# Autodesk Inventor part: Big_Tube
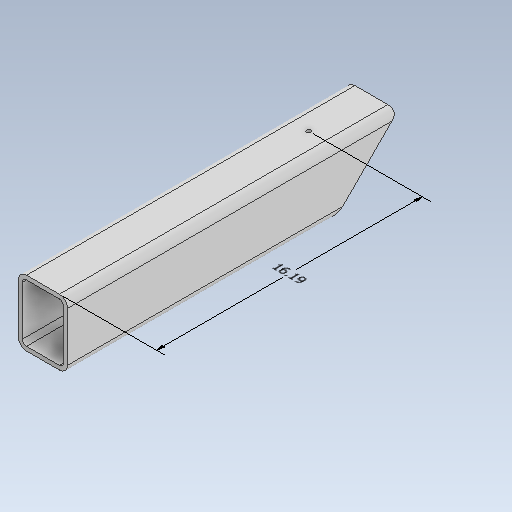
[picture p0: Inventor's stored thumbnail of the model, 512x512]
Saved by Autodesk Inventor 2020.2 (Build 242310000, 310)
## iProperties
Created: 2019-12
Part Number: Big_Tube
Material: Generic
Document SubType Name: Modeling
Designer: Patrick Everitt
Density: 1 g/cm^3
Appearance: Default
Description: 3x4 TUBE 20 Lg
Author: Patrick Everitt
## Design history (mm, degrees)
node "Annotations"
  node "Linear Dimension 1" dims "d34" = 411.1625 (derived)
sketch "Sketch1"
  geometry: L1 (-38.1, -38.1)-(-38.1, 38.1); L2 (-25.4, 50.8)-(25.4, 50.8); L3 (38.1, 38.1)-(38.1, -38.1); L4 (-25.4, -50.8)-(25.4, -50.8); L5 (-31.75, 38.1)-(-31.75, -38.1); L6 (-25.4, -44.45)-(25.4, -44.45); L7 (31.75, -38.1)-(31.75, 38.1); L8 (25.4, 44.45)-(-25.4, 44.45); A1 r 12.7 centre (-25.4, 38.1) between (-25.4, 50.8) and (-38.1, 38.1); A2 r 12.7 centre (25.4, 38.1) between (38.1, 38.1) and (25.4, 50.8); A3 r 12.7 centre (25.4, -38.1) between (25.4, -50.8) and (38.1, -38.1); A4 r 12.7 centre (-25.4, -38.1) between (-38.1, -38.1) and (-25.4, -50.8); A5 r 6.35 centre (-25.4, -38.1) between (-31.75, -38.1) and (-25.4, -44.45); A6 r 6.35 centre (25.4, -38.1) between (25.4, -44.45) and (31.75, -38.1); A7 r 6.35 centre (25.4, 38.1) between (31.75, 38.1) and (25.4, 44.45); A8 r 6.35 centre (-25.4, 38.1) between (-25.4, 44.45) and (-31.75, 38.1); 5 further points
  constraints: 16 end point, 16 point on circle, 8 centre point, 8 point on line, 8 tangent, 4 perpendicular, 3 equal radius, 1 vertical, 7 other
  dimensions: "d0" = 101.6 distance of point (-38.1, -50.8) point (-38.1, 50.8); "d2" = 76.2 distance of point (-38.1, 50.8) point (38.1, 50.8); "d3" = 90 deg angle of L1 L2 (derived); "d4" = 101.6 distance of point (38.1, 50.8) point (38.1, -50.8); "d5" = 90 deg angle of L2 L3 (derived); "d6" = 12.7 radius of A1 (derived); "d7" = 6.35 radial gap between concentric circles of A1 A8
extrude "Extrusion1" new body sketch "Sketch1" distance "d8" = 508; taper "d9" = 0 deg
sketch "Sketch2"
  geometry: L1 (0, 88.9)-(-508, 88.9) reference; L2 (0, -12.7)-(-508, -12.7) reference; L3 (0, 101.6)-(0, 82.55); L4 (0, 0)-(0, 76.2) reference; L5 (0, 82.55)-(-120.65, -38.1); L6 (-120.65, -38.1)-(45.483, -38.1); L7 (0, -12.7)-(-508, -12.7) reference; L8 (45.483, -38.1)-(45.483, 101.6); L9 (45.483, 101.6)-(0, 101.6)
  constraints: 10 end point, 2 perpendicular, 1 horizontal, 1 parallel, 1 point on line
  dimensions: "d19" = 6.35 distance of L3.end L1.start; "d20" = 45 deg angle of L1 L5; "d21" = 12.7 distance between parallel lines of L1 L9; "d22" = 127 distance between parallel lines of L1 L6; "d23" = 45.48263 distance between parallel lines of L8 L4
extrude "Extrusion2" cut sketch "Sketch2" extent not by distance; stored distance "d12" = 0; taper "d13" = 0 deg
sketch "Sketch4"
  geometry: L1 (-12.7, -6.35)-(-12.7, -508) reference; 2 further points
  dimensions: "d24" = 38.1 distance from line of L1 point (25.4, -96.838); "d25" = 96.8375 distance of point (25.4, 0) point (25.4, -96.838)
hole "Hole1" sketch "Sketch4" at (25.4, -96.838) diameter "d26" = 6.35; stored, may be unused: countersink angle "d30" = 82 deg, drill point angle "d32" = 118 deg; dims "d27" = 19.05, "d28" = 9.525, "d29" = 6.35, "d31" = 25.4
body "Solid1"
other parameters: "d33" = 2.13786 (derived)
